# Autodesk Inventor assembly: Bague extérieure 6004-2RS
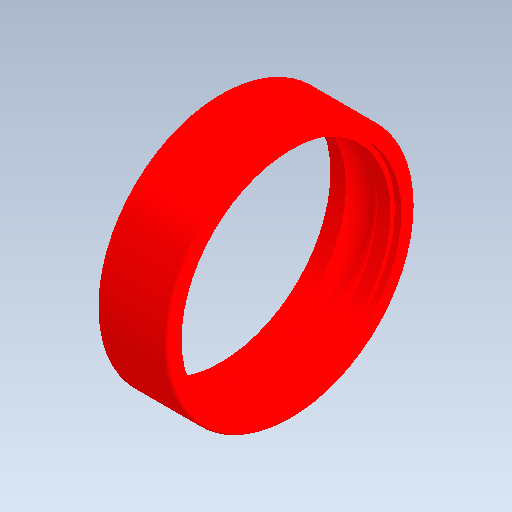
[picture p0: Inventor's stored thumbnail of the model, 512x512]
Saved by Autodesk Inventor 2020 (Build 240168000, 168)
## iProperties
Created: 2003-07
Part Number: Bague extérieure 6004-2RS
Document SubType Name: Assembly
Designer: Bruno
Author: Bruno
Sending System: SolidWorks 2011
Last Author: Professeur
Last Saved: 2014-11-10
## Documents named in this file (2)
- D:\Téléchargements-2016-17\scoot_elec\pièces à assembler\ROULEMENT 6004-2RS\Bague extérieure 6004-2RS.iam
- D:\Téléchargements-2016-17\scoot_elec\pièces à assembler\ROULEMENT 6004-2RS\Bague extérieure 6004-2RS.ipt
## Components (1 placed, 1 different names)
1. Bague extérieure 6004-2RS:1
